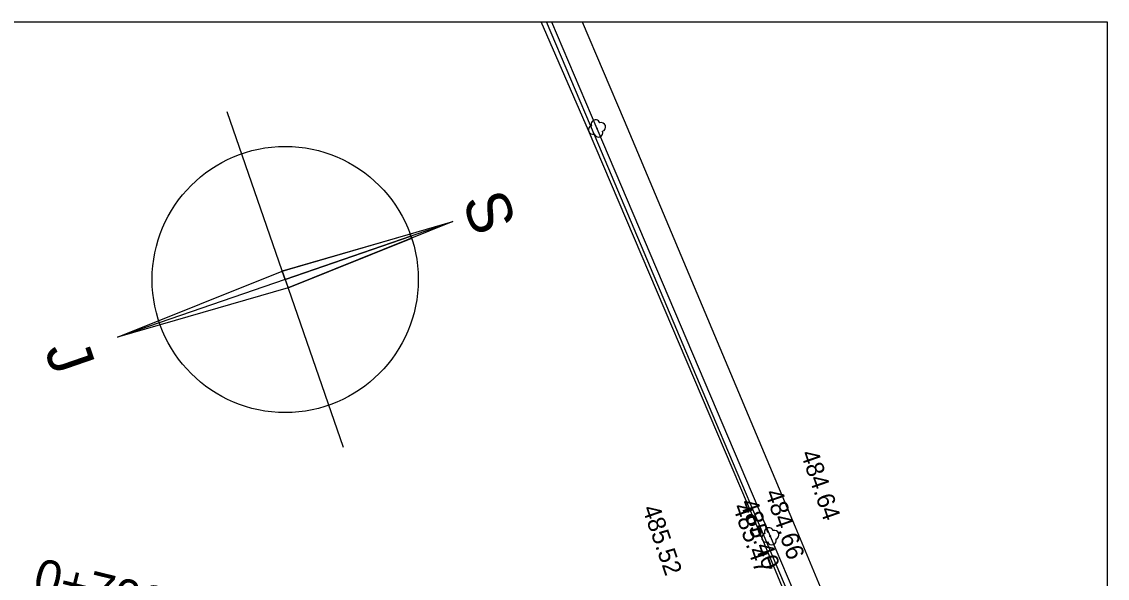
# Model space of a CAD drawing. Extents: x -636600 to -628587, y -1090963 to -1085869.
# Drawn here: x -629129.7 to -629007.3, y -1090728.6 to -1090665.8 of the extents above; entities that cross this region are included whole.
import ezdxf

# ---------------------------------------------------------------- set-up
doc = ezdxf.new("R2010")
doc.units = 0
for name, color, linetype in [('01_OBVOD PÚ', 7, 'Continuous'), ('08_LEGENDA_HV', 7, 'Continuous'), ('37', 7, 'Continuous'), ('42', 7, 'Continuous'), ('54', 7, 'Continuous'), ('55', 7, 'Continuous'), ('HEKTOMETRY100', 7, 'Continuous'), ('koty_vše', 7, 'Continuous')]:
    doc.layers.add(name, color=color, linetype=linetype)

msp = doc.modelspace()

# ---------------------------------------------------------------- linework, layer by layer
at = {"layer": '01_OBVOD PÚ'}
for points in [[(-629007.27, -1090790.22), (-629010.72, -1090787.72), (-629025.11, -1090773.13), (-629044.09, -1090728.27), (-629051.4, -1090710.98), (-629065.02, -1090678.77), (-629070.5, -1090665.82)], [(-629070.5, -1090665.82), (-629070.5, -1090665.82)]]:
    msp.add_lwpolyline(points, dxfattribs=at)
at = {"layer": '08_LEGENDA_HV'}
for p, q in [((-629847.27, -1090665.82), (-629007.27, -1090665.82)), ((-629007.27, -1090665.82), (-629007.27, -1090962.82)), ((-629099.95, -1090694.89), (-629106.48, -1090675.98)), ((-629100.28, -1090693.94), (-629081.05, -1090688.36)), ((-629099.95, -1090694.89), (-629081.05, -1090688.36)), ((-629081.05, -1090688.36), (-629099.63, -1090695.83)), ((-629118.86, -1090701.41), (-629100.28, -1090693.94)), ((-629099.95, -1090694.89), (-629118.86, -1090701.41)), ((-629099.95, -1090694.89), (-629100.28, -1090693.94)), ((-629099.95, -1090694.89), (-629093.43, -1090713.79)), ((-629099.95, -1090694.89), (-629099.63, -1090695.83)), ((-629099.63, -1090695.83), (-629118.86, -1090701.41))]:
    msp.add_line(p, q, dxfattribs=at)
for points in [[(-629085.86, -1090689.76), (-629100.28, -1090693.94), (-629099.95, -1090694.89), (-629085.77, -1090689.99)], [(-629085.77, -1090689.99), (-629099.95, -1090694.89), (-629099.63, -1090695.83), (-629085.69, -1090690.23)]]:
    msp.add_lwpolyline(points, dxfattribs=at)
msp.add_circle((-629099.95, -1090694.89), 15, dxfattribs=at)
for start, end in [(19.043, 19.9984), (18.0877, 19.043)]:
    msp.add_arc((-629099.95, -1090694.89), 15, start, end, dxfattribs=at)
at = {"layer": '37'}
for p, q in [((-629066.47, -1090665.82), (-629061.74, -1090676.96)), ((-629061.74, -1090676.96), (-629042.44, -1090722.76)), ((-629042.44, -1090722.76), (-629023.92, -1090767.51))]:
    msp.add_line(p, q, dxfattribs=at)
at = {"layer": '42'}
for p, q in [((-629065.77, -1090678.08), (-629071.08, -1090665.82)), ((-629046.1, -1090724.24), (-629065.77, -1090678.08)), ((-629025.92, -1090773.2), (-629046.1, -1090724.24))]:
    msp.add_line(p, q, dxfattribs=at)
at = {"layer": '54'}
for centre in [(-629064.8, -1090677.86), (-629045.26, -1090723.84)]:
    msp.add_circle(centre, 0.05, dxfattribs=at)
for centre, start, end in [((-629065.27, -1090678.02), 109.043, 289.043), ((-629064.96, -1090677.39), 19.043, 199.043), ((-629064.33, -1090677.7), 289.043, 109.043), ((-629064.64, -1090678.33), 199.043, 19.043), ((-629045.42, -1090723.37), 19.043, 199.043), ((-629045.73, -1090724), 109.043, 289.043), ((-629045.09, -1090724.31), 199.043, 19.043), ((-629044.78, -1090723.68), 289.043, 109.043)]:
    msp.add_arc(centre, 0.5, start, end, dxfattribs=at)
at = {"layer": '55'}
for p, q in [((-629069.91, -1090665.82), (-629064.8, -1090677.86)), ((-629064.8, -1090677.86), (-629045.26, -1090723.84)), ((-629045.26, -1090723.84), (-629029.49, -1090760.85))]:
    msp.add_line(p, q, dxfattribs=at)

# ---------------------------------------------------------------- texts
at = {"layer": '08_LEGENDA_HV'}
for s, p in [('S', (-629080.02, -1090685.98)), ('J', (-629127.12, -1090702.8))]:
    msp.add_text(s, height=5, rotation=289.043, dxfattribs=at).set_placement(p)
at = {"layer": 'HEKTOMETRY100'}
msp.add_text('0+700', height=4, rotation=346.3087, dxfattribs=at).set_placement((-629128.57, -1090730.13))
at = {"layer": 'koty_vše'}
for s, p in [('484.64', (-629041.86, -1090714.5)), ('484.66', (-629045.89, -1090718.92)), ('485.52', (-629059.71, -1090720.7)), ('485.47', (-629049.51, -1090720.5)), ('485.40', (-629048.69, -1090720.02))]:
    msp.add_text(s, height=2, rotation=289.043, dxfattribs=at).set_placement(p)

doc.saveas('drawing.dxf')
